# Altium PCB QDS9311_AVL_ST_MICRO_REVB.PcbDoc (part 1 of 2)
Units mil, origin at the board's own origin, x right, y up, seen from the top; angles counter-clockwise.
Board outline 2100 x 2774 mil, 6 copper layers (Top Layer, GND, INT1, PWR1, PWR2, Bottom Layer), stack 63.834 mil thick; 64 components, 29 nets, 286 pads, 246 vias.
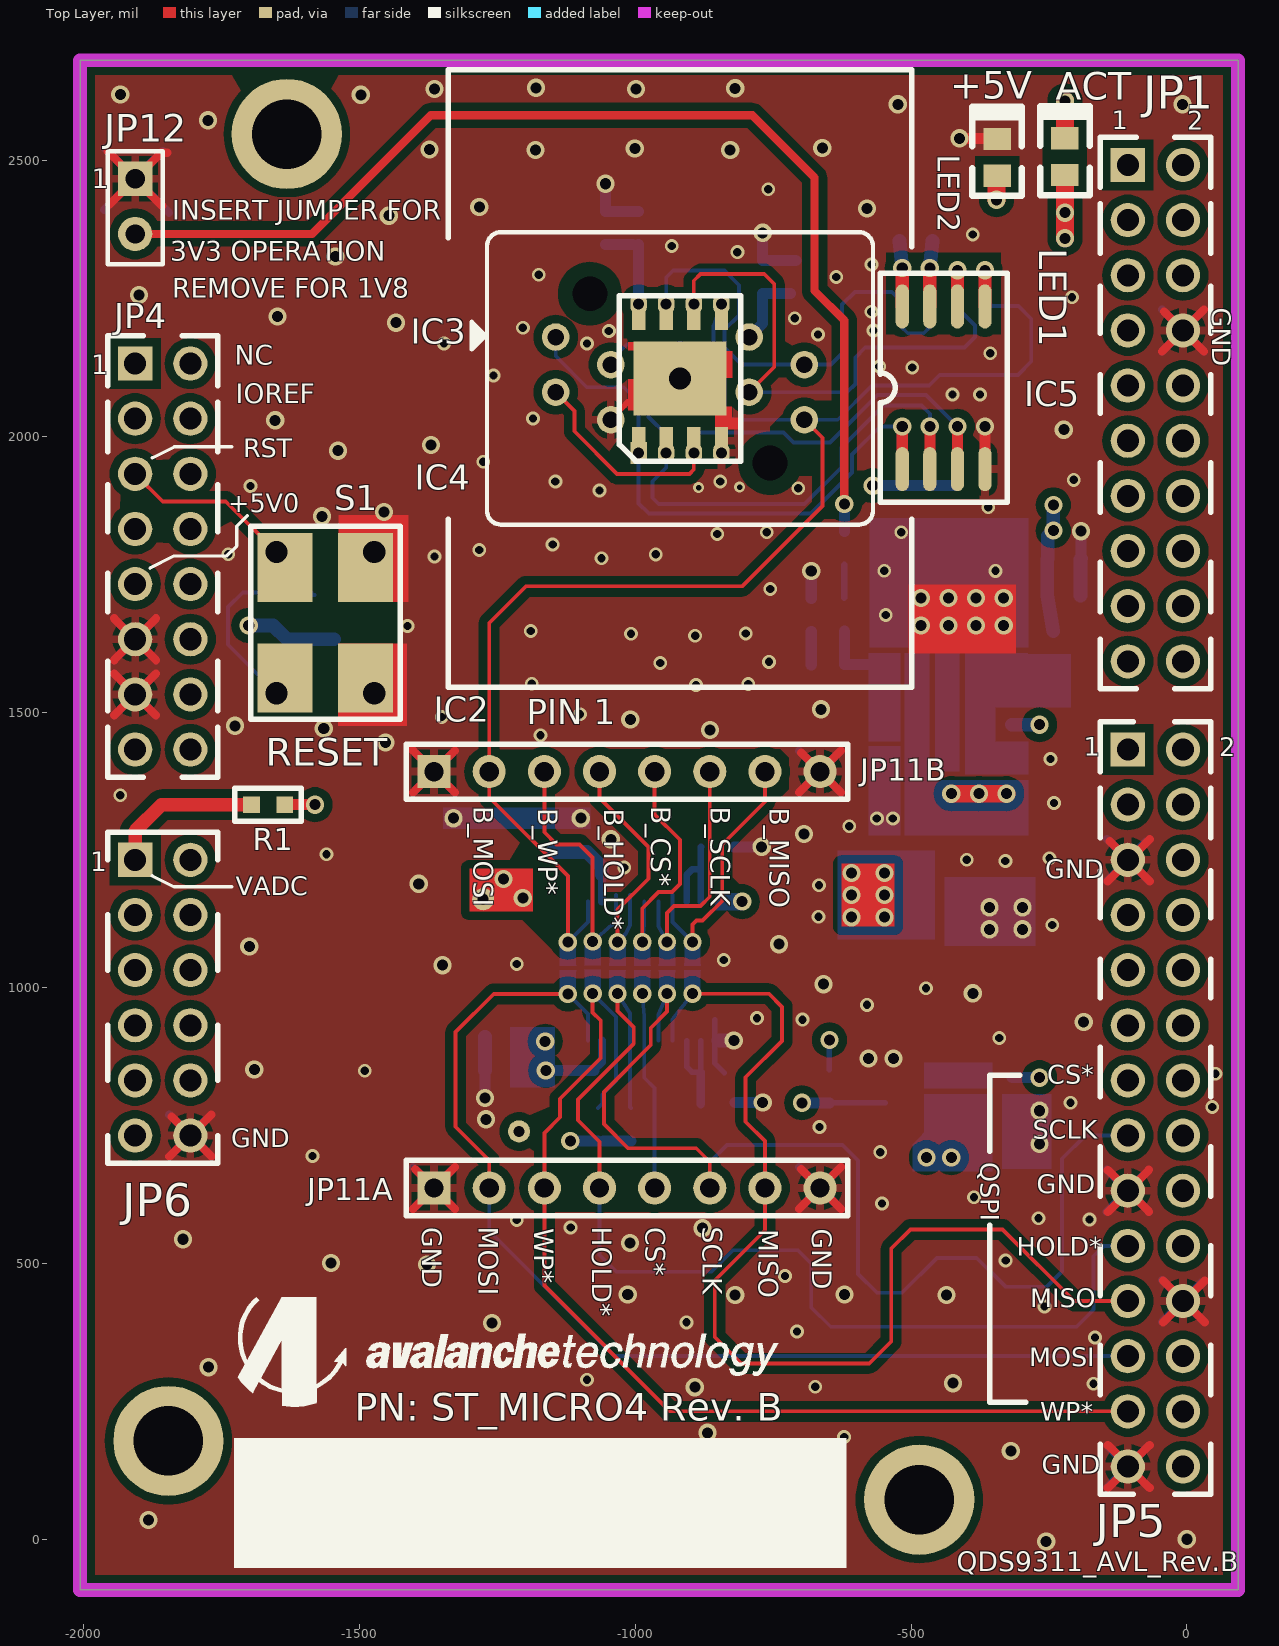
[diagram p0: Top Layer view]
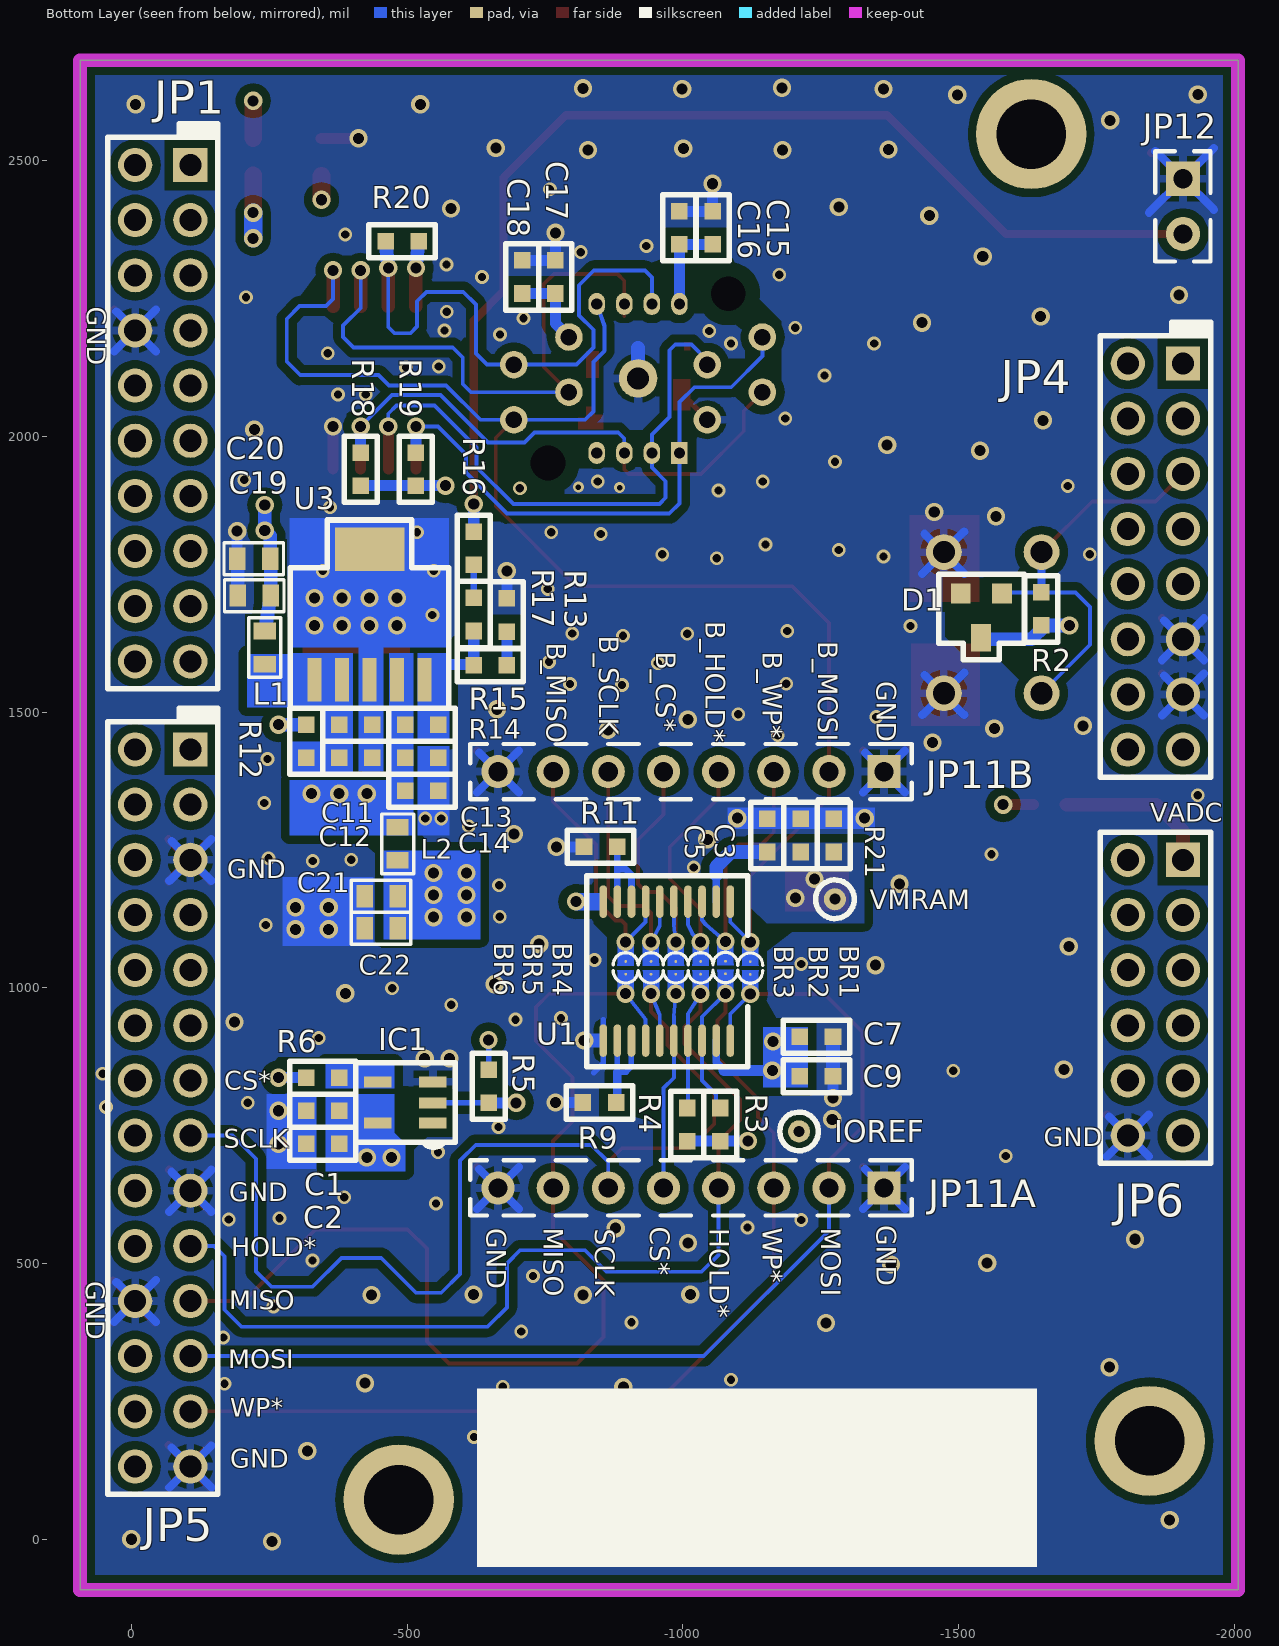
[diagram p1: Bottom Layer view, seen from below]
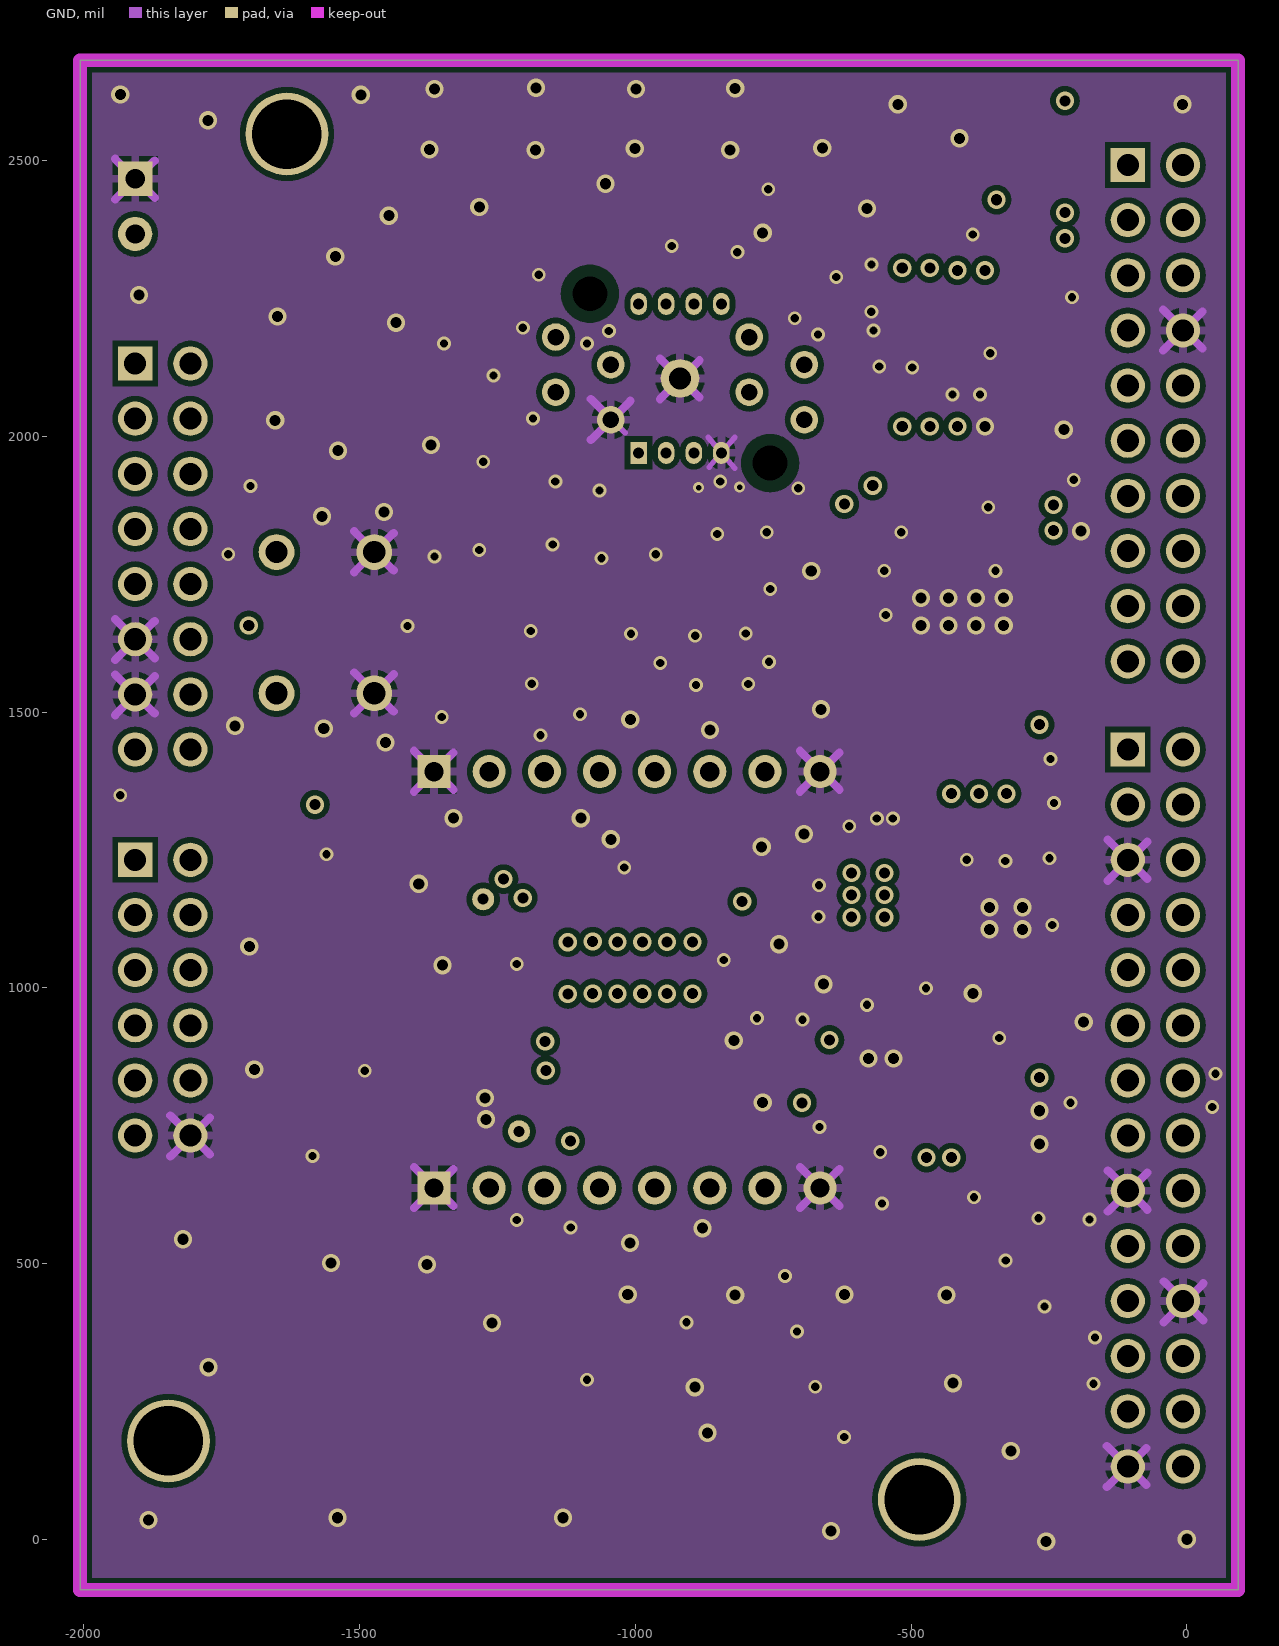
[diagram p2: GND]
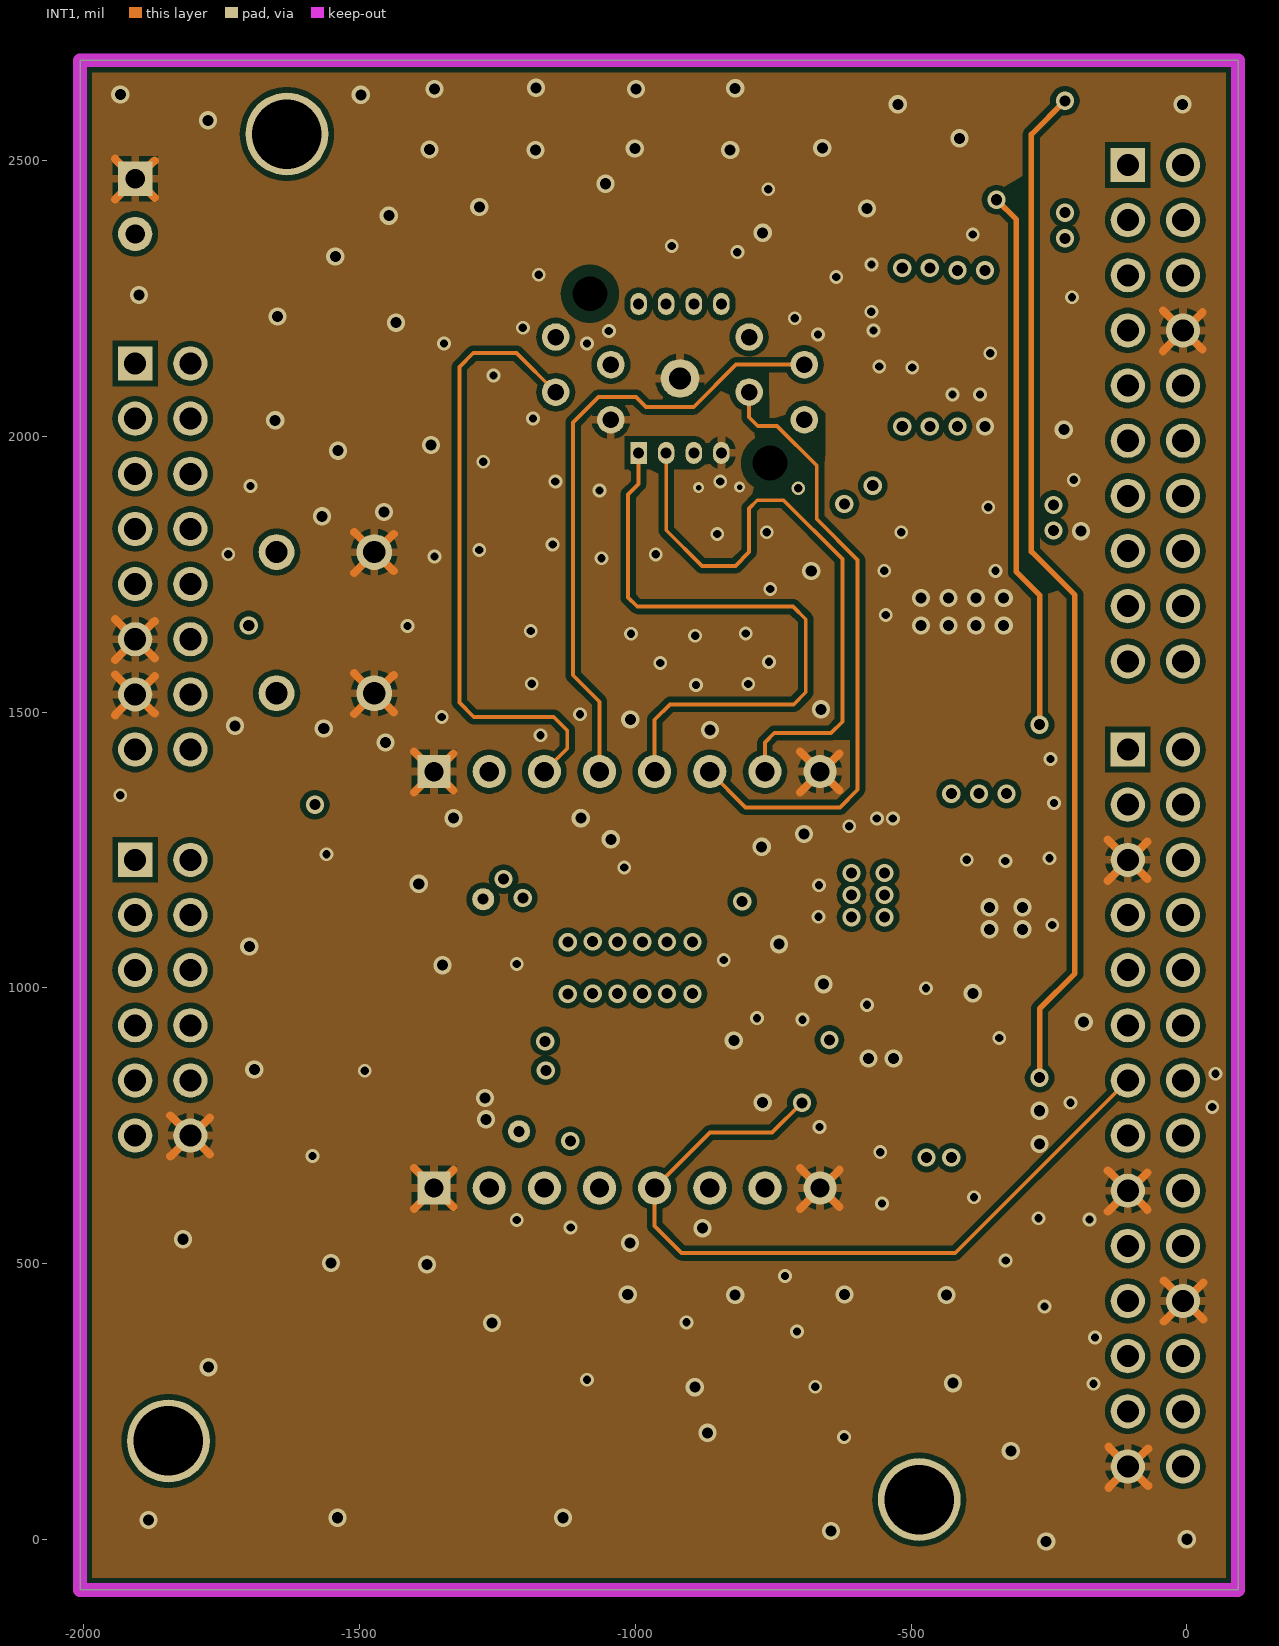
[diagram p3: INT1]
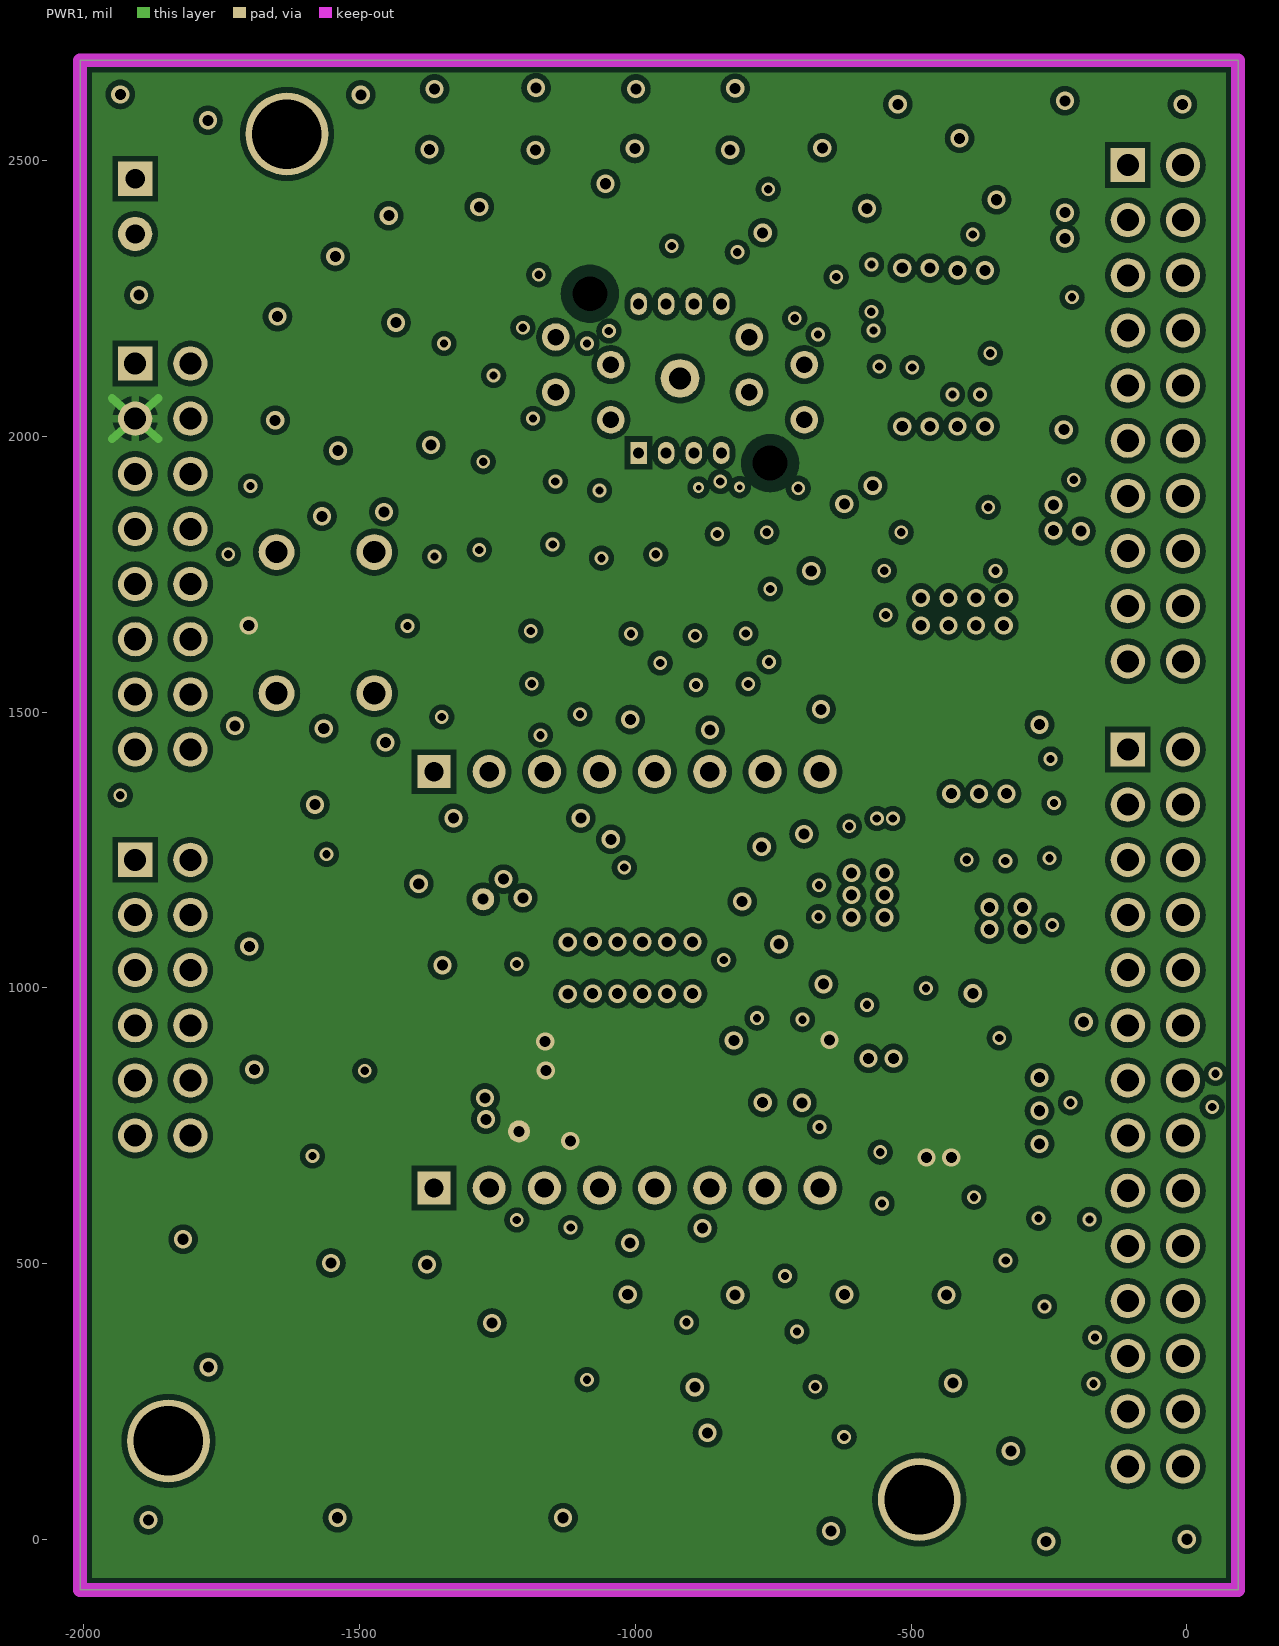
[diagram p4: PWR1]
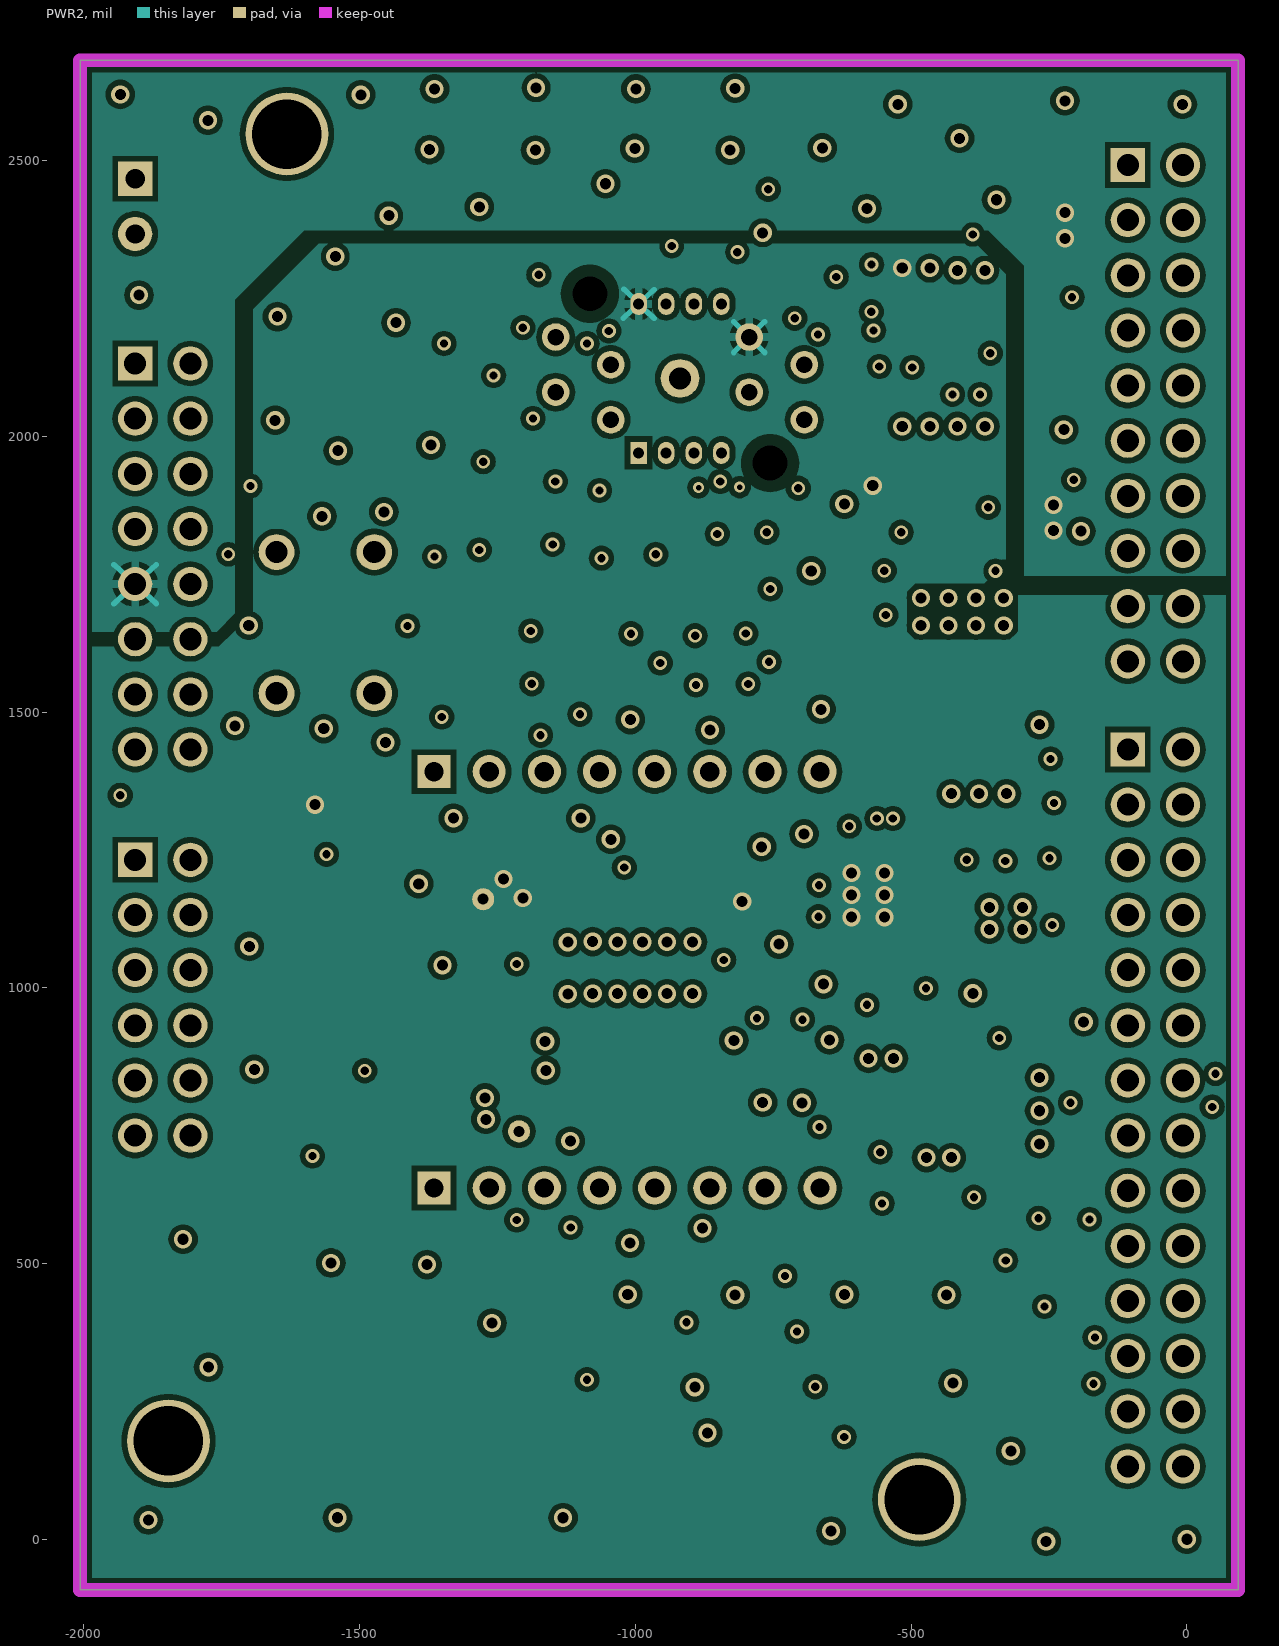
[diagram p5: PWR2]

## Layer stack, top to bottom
Top Solder: solder mask 1, Solder Resist, Dk 3.5
Top Layer: signal copper 6
Dielectric1: core 15, FR-4, Dk 4.2
GND: signal copper 2
Dielectric 8: prepreg 5, Dk 4.2
INT1: signal copper 1.417
Dielectric 10: core 10, Dk 4.2
PWR1: signal copper 2
Dielectric 11: prepreg 5, Dk 4.2
PWR2: signal copper 1.417
Dielectric 7: core 10, Dk 4.2
Bottom Layer: signal copper 6
Bottom Solder: solder mask 1, Solder Resist, Dk 3.5

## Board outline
-2007,-92 -2007,2682 93,2682 93,8 93,-92

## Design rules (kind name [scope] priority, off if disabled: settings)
Clearance Clearance_2 [OnLayer('Signal Layer 2')] p1 off: gap=10 ignorepadtopadclearanceinfootprint=FALSE except(0: Arc-Hole Track-Hole SMDPad-Hole THPad-Hole Via-Hole Fill-Hole Poly-Hole Region-Hole Text-Hole)
ComponentClearance [All] p1 off: gap=10 collisioncheckmode=3 verticalgap=10 showdistances=FALSE
FabricationTestPointUsage TestPointUsage [All] p1: valid=0 allowmultiple=FALSE
FabricationTestpoint Testpoint [(IsPad And (OnTopLayer Or OnBottomLayer))] p1: side=3 testpointundercomponent=TRUE minsize=40 maxsize=100 preferedsize=60 minholesize=0 maxholesize=40 preferedholesize=32 testpointgrid=1 allowsidetop=TRUE allowsidebottom=TRUE usegrid=TRUE gridtolerance=0.01
Height [All] p1 off: minheight=0 maxheight=1000 prefheight=500
HoleSize [All] p1 off: absolutevalues=TRUE maxlimit=100 minlimit=1 maxpercent=80.000 minpercent=20.000
PlaneConnect [All] p1: planeconnectstyle=Relief reliefexpansion=25 reliefentries=4 reliefconductorwidth=10 reliefairgap=12
PolygonConnect [All] p1: connectstyle=Direct reliefconductorwidth=10 reliefentries=4 polygonreliefangle="90 Angle" airgapwidth=10
RoutingVias [All] p1: holewidth=20 width=40 viastyle="Through Hole" minholewidth=20 minwidth=40 maxholewidth=20 maxwidth=40
ShortCircuit [InNet('NetA401_1') vs InNet('GND')] p1 off: allowed=FALSE
SolderMaskExpansion [All] p1: expansion=0 istentingtop=FALSE
Width Width_1 [All] p1: maxlimit=100 minlimit=6 preferedwidth=10 midlayer3_maxwidth=10 midlayer6_maxwidth=10 minimp=50.000000 maximp=50.000000 favimp=50.000000
23 further rules are at their usual default settings.

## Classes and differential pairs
net class GRP: C\S\ H\O\L\D\ MISO MOSI SCLK W\P\
net class B_GRP: B\_\C\S\ B\_\H\O\L\D\ B\_\W\P\ B_MISO B_MOSI B_SCLK
component class THERMAL: IC1 IC2 IC3 IC4 IC5 JP1 JP4 JP5 JP6 JP11A JP11B JP12 S1 U1 U3
component class PG0_ST_MICRO_4: BR1 BR2 BR3 BR4 BR5 BR6 C1 C2 C3 C5 C7 C9 D1 IC1 IOREF JP1 JP4 JP5 JP6 JP11A JP11B LED1 R1 R2 R3 R4 R5 R6 R9 R11 R21 S1 U1 VMRAM
component class PG1_ST_MICRO_4: C11 C12 C13 C14 C15 C16 C17 C18 C19 C20 C21 C22 IC2 IC3 IC4 IC5 JP12 L1 L2 LED2 R12 R13 R14 R15 R16 R17 R18 R19 R20 U3

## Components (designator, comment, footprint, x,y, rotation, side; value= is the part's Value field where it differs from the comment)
BR1 "NL" BR-603 -1122.39,1035.76 r90 bottom locked
BR2 "NL" BR-603 -1077.39,1036.76 r90 bottom locked
BR3 "NL" BR-603 -1032.37,1036.28 r90 bottom locked
BR4 "NL" BR-603 -987.39,1036.26 r90 bottom locked
BR5 "NL" BR-603 -942.42,1036.24 r90 bottom locked
BR6 "NL" BR-603 -896.42,1036.24 r90 bottom locked
C1 "10n" "0603 CAPACITOR_071713" -347,777 r0 bottom
C2 "1u" "0603 CAPACITOR_071713" -347,717 r0 bottom
C3 "10n" "0603 CAPACITOR_071713" -1213.55,1276.26 r90 bottom
C5 "1u" "0603 CAPACITOR_071713" -1153.55,1276.26 r90 bottom
C7 "10n" "0603 CAPACITOR_071713" -1242.39,911.26 r180 bottom
C9 "1u" "0603 CAPACITOR_071713" -1242.39,839.26 r180 bottom
C11 "10n" "0603 CAPACITOR_071713" -407,1477 r180 bottom
C12 "4.7u" "0603 CAPACITOR_071713" -407,1417 r180 bottom
C13 "10n" "0603 CAPACITOR_071713" -527,1417 r180 bottom
C14 "4.7u" "0603 CAPACITOR_071713" -527,1357 r180 bottom
C15 "1u" "0603 CAPACITOR_071713" -1054,2378 r90 bottom
C16 "10n" "0603 CAPACITOR_071713" -994,2378 r90 bottom
C17 "1u" "0603 CAPACITOR_071713" -769,2289 r90 bottom
C18 "10n" "0603 CAPACITOR_071713" -709,2289 r90 bottom
C19 "NL" 0603 -223,1711 r0 bottom
C20 "NL" 0603 -222,1778 r0 bottom
C21 "NL" 0603 -453,1166 r0 bottom
C22 "NL" 0603 -453,1108 r0 bottom
D1 "BAS40" SOT23_012105 -1541.5,1675 r0 bottom
IC1 "74LVC1G07DBVR" SOT25_030205 -497,792 r90 bottom
IC2 "AS2XXMA1G3A-WSON" "SOCKET WSON PLASTRONICS 08QN12T16050-M_020518" -919,2105 r90 top locked
IC3 "AS2XXMA1G3A-SOIC8" 652_SOP-1.27_8P -919,2105 r180 top locked
IC4 "AS2XXMA1G3A-WSON" "WSON8 6X5 MM WITH PAD_061714" -919,2105 r90 top locked
IC5 "AS2XXMA1G3A-SOIC8" "SO8 WIDE_071205" -441,2088 r0 top locked
IOREF "TP" "TEST POINT 40X20_010819" -1210.88,739.58 r270 bottom
JP1 "2X10_ML" 2X10-HEADER -57,2042 r270 top locked
JP4 "2X8_ML" 2X8-HEADER -1857,1782 r270 top locked
JP5 "2X14_ML" 2X14-HEADER -57,782 r270 top locked
JP6 "2X6_ML" "2X6 HEADER_082710" -1857,982 r270 top locked
JP11A "HEADER_8PIN" "1X8 HEADER ARDUINO STACKABLE_010719" -1015,637 r0 top locked
JP11B "HEADER_8PIN" "1X8 HEADER ARDUINO STACKABLE_010719" -1015,1392 r0 top locked
JP12 "3.3V ENABLE" "1X2 HEADER WITH SHUNT_051914" -1907,2467 r270 top
L1 "BLM18SG121TN1D" 0603 -242,1617 r270 bottom
L2 "BLM18SG121TN1D" 0603 -483,1261 r270 bottom
LED1 "GREEN" "LED 0805 GREEN_032906" -221,2507 r270 top locked
LED2 "RED" "LED 0805 GREEN_032906" -344,2506 r270 top
R1 "33" "0603 RESISTOR_071013" -1666,1332 r180 top
R2 "22K" "0603 RESISTOR_071013" -1650,1687 r270 bottom
R3 "22K" "0603 RESISTOR_071013" -1068,752 r270 bottom
R4 "22K" "0603 RESISTOR_071013" -1008,752 r270 bottom
R5 "22K" "0603 RESISTOR_071013" -648,821.5 r90 bottom
R6 "2K" "0603 RESISTOR_071013" -347,837 r0 bottom
R9 "100" "0603 RESISTOR_071013" -849,792 r180 bottom
R11 "100" "0603 RESISTOR_071013" -850.88,1255.58 r180 bottom
R12 "2K" "0603 RESISTOR_071013" -317,1447 r270 bottom
R13 "0" "0603 RESISTOR_071013" -681,1676 r90 bottom
R14 "105K, 1%" "0603 RESISTOR_071013" -527,1477 r0 bottom
R15 "30.9K, 1%" "0603 RESISTOR_071013" -651,1585 r0 bottom
R16 "0" "0603 RESISTOR_071013" -621,1797 r90 bottom
R17 "28.7K, 1%" "0603 RESISTOR_071013" -621,1677 r270 bottom
R18 "22K" "0603 RESISTOR_071013" -416,1940.5 r270 bottom
R19 "22K" "0603 RESISTOR_071013" -516,1940.5 r270 bottom
R20 "22K" "0603 RESISTOR_071013" -491,2354 r180 bottom
R21 "100K" "0603 RESISTOR_071013" -1273.55,1276.26 r270 bottom
S1 "SWRST" "SWITCH TE PB 1825910-6_112915" -1562,1662 r180 top locked
U1 "TXS0108E" TSSOP_20PIN -970.98,1030.26 r270 bottom locked
U3 "MCP1825T-ADJE/DC" "SOT223-6 REGULATOR_010419" -432,1677 r180 bottom
VMRAM "TP" "TEST POINT 40X20_010819" -1275.88,1160.58 r270 bottom

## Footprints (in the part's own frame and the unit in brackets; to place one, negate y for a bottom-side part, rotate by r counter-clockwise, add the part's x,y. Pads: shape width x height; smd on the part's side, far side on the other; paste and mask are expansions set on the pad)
"1X2 HEADER WITH SHUNT_051914" [mil] "TH"
  rect 62x62 hole 35: 1(0,0)
  round 62 hole 35: 2(100,0)
  silkscreen extent -50,-50 155,50
"1X8 HEADER ARDUINO STACKABLE_010719" [mil] "TH"
  rect 60x60 hole 35: 1(-350,0)
  round 60 hole 35: 2(-250,0) 3(-150,0) 4(-50,0) 5(50,0) 6(150,0) 7(250,0) 8(350,0)
  silkscreen extent -400,-50 400,50
"2X6 HEADER_082710" [mil] "TH"
  rect 62x62 hole 40: 1(-250,-50)
  round 62 hole 40: 2(-250,50) 3(-150,-50) 4(-150,50) 5(-50,-50) 6(-50,50) 7(50,-50) 8(50,50) 9(150,-50) 10(150,50) 11(250,-50) 12(250,50)
  silkscreen extent -300,-100 300,100
2X8-HEADER [mil] "TH"
  rect 62x62 hole 40: 1(-350,-50)
  round 62 hole 40: 2(-350,50) 3(-250,-50) 4(-250,50) 5(-150,-50) 6(-150,50) 7(-50,-50) 8(-50,50) 9(50,-50) 10(50,50) 11(150,-50) 12(150,50) 13(250,-50) 14(250,50) 15(350,-50) 16(350,50)
  silkscreen extent -400,-100 400,100
2X10-HEADER [mil] "TH"
  rect 62x62 hole 40: 1(-450,-50)
  round 62 hole 40: 2(-450,50) 3(-350,-50) 4(-350,50) 5(-250,-50) 6(-250,50) 7(-150,-50) 8(-150,50) 9(-50,-50) 10(-50,50) 11(50,-50) 12(50,50) 13(150,-50) 14(150,50) 15(250,-50) 16(250,50) 17(350,-50) 18(350,50) 19(450,-50) 20(450,50)
  silkscreen extent -500,-100 500,100
2X14-HEADER [mil] "TH"
  rect 62x62 hole 40: 1(-650,-50)
  round 62 hole 40: 2(-650,50) 3(-550,-50) 4(-550,50) 5(-450,-50) 6(-450,50) 7(-350,-50) 8(-350,50) 9(-250,-50) 10(-250,50) 11(-150,-50) 12(-150,50) 13(-50,-50) 14(-50,50) 15(50,-50) 16(50,50) 17(150,-50) 18(150,50) 19(250,-50) 20(250,50) 21(350,-50) 22(350,50) 23(450,-50) 24(450,50) 25(550,-50) 26(550,50) 27(650,-50) 28(650,50)
  silkscreen extent -700,-100 700,100
0603 [mil]
  rect 30x40 smd: 1(-30,0) 2(30,0)
  silkscreen extent -54,-29 54,29
"0603 CAPACITOR_071713" [mil] "SMT"
  rect 30x30 smd mask+2: 1(-30,0) 2(30,0)
  silkscreen extent -60,-30 60,30
"0603 RESISTOR_071013" [mil] "SM"
  rect 30x30 smd mask+2: 1(-30,0) 2(30,0)
  silkscreen extent -60,-30 60,30
652_SOP-1.27_8P [mil]
  round 50 hole 30: 1(225.39,-75) 2(125.39,-25) 3(225.39,25) 4(125.39,75) 5(-225.39,75) 6(-125.39,25) 7(-225.39,-25) 8(-125.39,-75)
  round 40 hole 63 unplated: HOLE1.6_NP(-163.39,153.54) HOLE1.6_NP(163.39,-153.54)
  round 40 on Mech2: HOLE1.6_NP(163.39,-153.54)
  round 50 on Mech2: ORIGIN(0,0)
  silkscreen extent -350,-265 378,265
BR-603 [mil] "BR-603"
  round 5 smd: 1(-11.5,0) 2(11.5,0)
  Top Layer region: 5.31,14.94 6.6,14.77 7.88,14.49 9.13,14.1 10.34,13.59 11.5,12.99 12.6,12.29 13.64,11.49 14.61,10.61 15.49,9.64 16.29,8.6 16.99,7.5 17.59,6.34 18.1,5.13 18.49,3.88 18.77,2.6 18.94,1.31 19,0 18.94,-1.31 18.77,-2.6 18.49,-3.88 18.1,-5.13 17.59,-6.34 16.99,-7.5 16.29,-8.6 15.49,-9.64 14.61,-10.61 13.64,-11.49 12.6,-12.29 11.5,-12.99 10.34,-13.59 9.13,-14.1 7.88,-14.49 6.6,-14.77 5.31,-14.94 4,-15 4,15
  Top Layer region: -4.04,-15 -5.35,-14.94 -6.64,-14.77 -7.92,-14.49 -9.17,-14.1 -10.38,-13.59 -11.54,-12.99 -12.64,-12.29 -13.68,-11.49 -14.65,-10.61 -15.53,-9.64 -16.33,-8.6 -17.03,-7.5 -17.63,-6.34 -18.14,-5.13 -18.53,-3.88 -18.81,-2.6 -18.98,-1.31 -19.04,0 -18.98,1.31 -18.81,2.6 -18.53,3.88 -18.14,5.13 -17.63,6.34 -17.03,7.5 -16.33,8.6 -15.53,9.64 -14.65,10.61 -13.68,11.49 -12.64,12.29 -11.54,12.99 -10.38,13.59 -9.17,14.1 -7.92,14.49 -6.64,14.77 -5.35,14.94 -4.04,15
  silkscreen extent -27,-23 27,23
"LED 0805 GREEN_032906" [mil] "SMT"
  rect 40x50 smd: A(33.46,0) C(-33.46,0)
  silkscreen extent -92,-45 70,45
"SO8 WIDE_071205" [mil] "SMT"
  oval 24x80 smd: 1(-75,-147.5) 2(-25,-147.5) 3(25,-147.5) 4(75,-147.5) 5(75,147.5) 6(25,147.5) 7(-25,147.5) 8(-75,147.5)
  silkscreen extent -115,-208 115,208, body extent -107,-160 107,159, height 69
"SOCKET WSON PLASTRONICS 08QN12T16050-M_020518" [mil] "TH"
  rect 40x30 hole 20: 1(-135,75)
  oval 40x30 hole 20: 2(-135,25) 3(-135,-25) 4_EP(-135,-75) 5(135,-75) 6(135,-25) 7(135,25) 8(135,75)
  round 70 hole 40 unplated: 9(0,0)
  silkscreen extent -560,-420 560,420, body extent -540,-400 540,400, height 570
SOT23_012105 [mil] "SMT"
  rect 36x36 smd: 1(-37.5,-40) 2(37.5,-40)
  rect 36x50 smd: 3(0.5,40)
  silkscreen extent -78,-75 78,80
SOT25_030205 [mil] "SMT"
  round 30 on Mech1 paste+0 mask+1.97: 1(-75,-65)
  rect 20x50 smd mask+1.97: 1(-37.5,-50) 2(-0.5,-50) 3(37.5,-50) 4(37.5,50) 5(-37.5,50)
  silkscreen extent -81,-90 72,90
"SOT223-6 REGULATOR_010419" [mm] "SMT"
  rect 0.65x2 smd mask+0.05: 1(-2.54,-3) 2(-1.27,-3) 3(0,-3) 4(1.27,-3) 5(2.54,-3)
  rect 3.2x2 smd: 3(0,3)
  silkscreen extent -3.65,-4.33 3.65,4.35
"SWITCH TE PB 1825910-6_112915" [mil] "TH"
  round 65 hole 40: 1(88.58,127.95) 2(88.58,-127.95) 3(-88.58,127.95) 4(-88.58,-127.95)
  rect 30x60 on Mech2: ""(-75,110) ""(-75,-110) ""(75,110) ""(75,-110)
  rect 100x125 smd mask-1000: ""(-73,100) ""(-73,-100) ""(73,100) ""(73,-100)
  rect 50x70 on Mech2 mask-1000: ""(-50,75) ""(-50,-75) ""(50,75) ""(50,-75)
  round 60 on Mech2: ""(0,0)
  silkscreen extent -136,-175 136,175
"TEST POINT 40X20_010819" [mil] "TH"
  round 40 hole 20: 1(0,0)
  silkscreen extent -35,-35 35,35
TSSOP_20PIN [mm] "SM FP"
  oval 1.5x0.35 smd mask+0.038: 1(-3.2,2.925) 2(-3.2,2.275) 3(-3.2,1.625) 4(-3.2,0.975) 5(-3.2,0.325) 6(-3.2,-0.325) 7(-3.2,-0.975) 8(-3.2,-1.625) 9(-3.2,-2.275) 10(-3.2,-2.925) 11(3.2,-2.925) 12(3.2,-2.275) 13(3.2,-1.625) 14(3.2,-0.975) 15(3.2,-0.325) 16(3.2,0.325) 17(3.2,0.975) 18(3.2,1.625) 19(3.2,2.275) 20(3.2,2.925)
  silkscreen extent -4.4,-3.68 4.4,3.73
"WSON8 6X5 MM WITH PAD_061714" [mil] "SMT"
  rect 50x24 smd mask+2: 1(-113.11,75) 2(-113.11,25) 3(-113.11,-25) 4_EP(-113.11,-75) 5(113.11,-75) 6(113.11,-25) 7(113.11,25) 8(113.11,75)
  rect 133.86x169.29 smd paste-95 mask+0: 9(0,0)
  silkscreen extent -150,-110 150,110, body extent -117,-98 119,98, height 30

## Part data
BR1 BR2 BR3 BR4 BR5 BR6: library part R-US_R0805, "<B>RESISTOR</B>, American symbol"
C1 C2 C3 C5 C7 C9 C11 C12 C13 C14 C15 C16 C17 C18: library part C-USC0603, "<B>CAPACITOR</B>, American symbol"
C19 C20 C21 C22: library part C-USC0805, "<B>CAPACITOR</B>, American symbol"
D1: "<b>Silicon Schottky Diodes</b><p> / General-purpose diode for high-speed switching"
IC2 IC4: "AVALANCHE TECHNOLOGY SPI SPnvSRAM - WSON 8 PACKAGE"
IC3 IC5: "AVALANCHE TECHNOLOGY SPI SPnvSRAM - SOIC8 PACKAGE"
IOREF VMRAM: library part "TEST POINT 1"
JP12: library part PINHD-1X2, "<b>PIN HEADER</b>"
L1 L2: library part FB
LED1 LED2: library part LEDCHIP-LED0805, "<b>LED</b><p> / <u>OSRAM</u>:<br> /  / - <u>CHIPLED</u><br> / LG R971, LG N971, LY N971, LG Q971, LY Q971, LO R971, LY R971 / LH N974, LH R974<br> / LS Q976, LO Q976, LY Q976<br> / LO Q996<br> /  / - <u>Hyper CHIPLED</u><br> / LW Q18S<br> / LB Q993, LB Q99A, LB R99A<br> /  / - <u>SideLED</u><br> / LS A670, LO A670, LY A670, LG A670, LP A670<br> / LB A673, LV A673, LT A673, LW A673<br> / LH A674<br> / LY A675<br> / LS A676, LA A676, LO A676, LY A676, LW A676<br> / LS A679, LY A679, LG A679<br> /  / -  <u>Hyper Micro SIDELED®</u><br> / LS Y876, LA Y876, LO Y876, LY Y876<br> / LT Y87S<br> /  / - <u>SmartLED</u><br> / LW L88C, LW L88S<br> / LB L89C, LB L89S, LG L890<br> / LS L89K, LO L89K, LY L89K<br> / LS L896, LA L896, LO L896, LY L896<br> /  / - <u>TOPLED</u><br> / LS T670, LO T670, LY T670, LG T670, LP T670<br> / LSG T670, LSP T670, LSY T670, LOP T670, LYG T670<br> / LG T671, LOG T671, LSG T671<br> / LB T673, LV T673, LT T673, LW T673<br> / LH T674<br> / LS T676, LA T676, LO T676, LY T676, LB T676, LH T676, LSB T676, LW T676<br> / LB T67C, LV T67C, LT T67C, LS T67K, LO T67K, LY T67K, LW E67C<br> / LS E67B, LA E67B, LO E67B, LY E67B, LB E67C, LV E67C, LT E67C<br> / LW T67C<br> / LS T679, LY T679, LG T679<br> / LS T770, LO T770, LY T770, LG T770, LP T770<br> / LB T773, LV T773, LT T773, LW T773<br> / LH T774<br> / LS E675, LA E675, LY E675, LS T675<br> / LS T776, LA T776, LO T776, LY T776, LB T776<br> / LHGB T686<br> / LT T68C, LB T68C<br> /  / - <u>Hyper Mini TOPLED®</u><br> / LB M676<br> /  / - <u>Mini TOPLED Santana®</u><br> / LG M470<br> / LS M47K, LO M47K, LY M47K / <p> / Source: http://www.osram.convergy.de<p> /  / <u>LUXEON:</u><br> / - <u>LUMILED®</u><br> / LXK2-PW12-R00, LXK2-PW12-S00, LXK2-PW14-U00, LXK2-PW14-V00<br> / LXK2-PM12-R00, LXK2-PM12-S00, LXK2-PM14-U00<br> / LXK2-PE12-Q00, LXK2-PE12-R00, LXK2-PE12-S00, LXK2-PE14-T00, LXK2-PE14-U00<br> / LXK2-PB12-K00, LXK2-PB12-L00, LXK2-PB12-M00, LXK2-PB14-N00, LXK2-PB14-P00, LXK2-PB14-Q00<br> / LXK2-PR12-L00, LXK2-PR12-M00, LXK2-PR14-Q00, LXK2-PR14-R00<br> / LXK2-PD12-Q00, LXK2-PD12-R00, LXK2-PD12-S00<br> / LXK2-PH12-R00, LXK2-PH12-S00<br> / LXK2-PL12-P00, LXK2-PL12-Q00, LXK2-PL12-R00 / <p> / Source: www.luxeon.com<p> /  / <u>KINGBRIGHT:</U><p> / KA-3528ASYC<br> / Source: www.kingbright.com"
R1 R2 R3 R4 R5 R6 R9 R11 R12 R13 R14 R15 R16 R17 R18 R19 R20 R21: library part R-US_R0603, "<B>RESISTOR</B>, American symbol"
S1: library part MOMENTARY-SWITCH-SPST-2-SMD-5.2MM, "<h3>Momentary Switch (Pushbutton) - SPST - Two Circuits</h3> / <p>Normally-open (NO) SPST momentary switches (buttons, pushbuttons). Schematic symbol includes two switch circuits.</p> / <h4>Variants</h4> / <ul> / <li><b>SMD-4.6MMX2.8MM</b> -  4.60mm x 2.80mm Tactile Momentary Button Switch  - Used on <a href=\"https://www.sparkfun.com/products/13664\">SparkFun SAMD21 Mini Breakout</a></li> / <li><b>SMD-5.2MM</b> - <a href=\"https://www.sparkfun.com/products/8720\">Mini Pushbutton Switch - SMD</a> - Used on <a href=\"https://www.sparkfun.com/products/11114\">Arduino Pro Mini</a></li> / </ul>"

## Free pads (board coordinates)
  round 45 on Bottom Overlay: 2(-585,681) ""(-1152.39,1152.26)
  round 60 on Mech9: ""(-1907,1232) ""(-1907,2132)
  round 200 / inner round 150 / far side round 200 hole 126 mask+0: ""(-1846.64,178.28) ""(-1631.86,2548.18) ""(-485.17,71.9)
  round 45 on Top Overlay: ""(-1706,1444)

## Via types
v1: diameter 33, hole 20, Top Layer to Bottom Layer, tented both sides, 143 vias
v2: diameter 25, hole 15, Top Layer to Bottom Layer, tented both sides, 101 vias
v3: diameter 20, hole 10, Top Layer to Bottom Layer, tented both sides, 2 vias

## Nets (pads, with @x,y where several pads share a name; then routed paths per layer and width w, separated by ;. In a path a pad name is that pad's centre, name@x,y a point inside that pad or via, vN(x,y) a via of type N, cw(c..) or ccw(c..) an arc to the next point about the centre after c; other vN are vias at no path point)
+5V0: C19.1 C20.1 JP4.9 L1.1 LED1.A | length 604.7
  Top Layer w32: v1(-221,2359) v1(-221,2405.54) LED1.A@-221,2473.54
  PWR2 w10: -1945.5,1696.46 JP4.9@-1907,1732 ; -1945.5,1767.54 JP4.9@-1907,1732 ; -1868.5,1696.46 JP4.9@-1907,1732 ; -1868.5,1767.54 JP4.9@-1907,1732
  Bottom Layer w25: L1.1@-242,1647 C19.1@-253,1711 -253,1777 C20.1@-252,1778 -252,1819 v1(-242,1829) v1(-242,1875.54)
  Bottom Layer w33: v1(-221,2359) v1(-221,2405.54)
B\_\C\S\: BR4.2 IC2.1 IC3.1 IC4.1 IC5.1 JP11B.5 R19.1 U1.5 | length 2728.9
  Top Layer w7: IC2.1@-994,1970 IC4.1@-994,1991.89 ; v1(-987.39,1083.21) -987.39,1144.02 -957.79,1173.62 -933.75,1173.62 -919,1188.37 -919,1268.42 -965,1314.42 JP11B.5@-965,1392
  Top Layer w20: IC5.1@-516,1940.5 v1(-516,2018)
  INT1 w7: IC2.1@-994,1970 -994,1913.22 -1013,1894.22 -1013,1707.76 -996.51,1691.26 -713.99,1691.26 -691,1668.28 -691,1535.8 -712.8,1514 -937.12,1514 -965,1486.12 JP11B.5@-965,1392
  Bottom Layer w7: IC3.1@-1144.39,2180 -1144.39,2145.39 -1088,2089 -1021,2089 -994,2062 IC2.1@-994,1970 -994,1878.49 -975.51,1860 -681.21,1860 -607,1934.21 -607,1967 -556,2018 v1(-516,2018) ; BR4.2@-987.39,1047.76 v1(-987.39,1083.21) -983.78,1114.49 U1.5@-983.78,1156.24
  Bottom Layer w20: R19.1@-516,1970.5 v1(-516,2018)
B\_\H\O\L\D\: BR3.2 IC2.7 IC3.7 IC4.7 IC5.7 JP11B.4 R20.1 U1.4 | length 2727.7
  Top Layer w7: JP11B.4@-1065,1392 -1065,1344 -976.34,1255.34 -976.34,1197.66 -1032.37,1141.63 v1(-1032.37,1083.24)
  Top Layer w24: IC5.7@-466,2235.5 v1(-466,2305)
  INT1 w7: JP11B.4@-1065,1392 -1065,1518.73 -1113,1566.73 -1113,2024.92 -1066.75,2071.17 -998.67,2071.17 -980.5,2053 -894.14,2053 -817.14,2130 IC3.7@-693.61,2130
  Bottom Layer w7: BR3.2@-1032.37,1047.78 -1032.37,1083.14 v1(-1032.37,1083.24) -1017.75,1097.75 -1009.37,1114.69 U1.4@-1009.37,1156.24 U1.4@-1009.37,1168.2 ; IC2.7@-944,2240 -944,2287.73 -931.23,2300.5 -838.64,2300.5 -812,2273.86 -812,2219.17 -838,2193.17 -838,2160.72 -807.28,2130 IC3.7@-693.61,2130 -645,2130 -625,2150 -625,2239 -602,2262 -535,2262 -518,2245 -518,2199 -506,2187 -477,2187 -466,2198 v1(-466,2305)
  Bottom Layer w25: v1(-466,2305) R20.1@-461,2354
B\_\W\P\: BR2.2 IC2.3 IC3.3 IC4.3 IC5.3 JP11B.3 R18.1 U1.3 | length 2729.3
  Top Layer w7: JP11B.3@-1165,1392 -1165,1282 -1143,1260 -1101.31,1260 -1077.39,1236.09 v1(-1077.39,1083.71) ; IC3.3@-1144.39,2080 -1110.5,2046.11 -1110.5,2009.12 -1033.07,1931.69 -901.86,1931.69 -894,1939.55 IC2.3@-894,1970 IC4.3@-894,1991.89 ; v1@-1077.92,1083.19 v1@-1077.39,1082.66
  Top Layer w20: IC5.3@-416,1940.5 v1(-416,2018)
  INT1 w7: JP11B.3@-1165,1392 -1123.39,1433.61 -1123.39,1466.39 -1148,1491 -1293,1491 -1319,1517 -1319,2126 -1294,2151 -1215.39,2151 IC3.3@-1144.39,2080
  Bottom Layer w7: BR2.2@-1077.39,1048.26 v1(-1077.39,1083.71) -1041.62,1114.69 -1034.96,1122.97 U1.3@-1034.96,1156.24 U1.3@-1034.96,1168.2 ; IC2.3@-894,1970 -894,1996 -883,2007 -731,2007 -713,1989 -647,1989 -561,2075 -473,2075 v1(-416,2018)
  Bottom Layer w20: R18.1@-416,1970.5 v1(-416,2018)
B_MISO: BR6.2 IC2.2 IC3.2 IC4.2 IC5.2 JP11B.7 U1.7 | length 2729
  Top Layer w7: v1(-896.42,1083.19) -896.42,1114.58 -889,1122 -878,1122 -842.43,1157.57 -842.43,1259.88 -765,1337.31 JP11B.7@-765,1392
  Top Layer w20: IC5.2@-466,1940.5 v1(-466,2018)
  INT1 w7: IC2.2@-944,1970 -944,1829.68 -879.32,1765 -818.59,1765 -793.61,1789.99 -793.61,1869.39 -779,1884 -731,1884 -624.67,1777.67 -624.67,1482.33 -645,1462 -748,1462 -765,1445 JP11B.7@-765,1392
  Bottom Layer w7: IC3.2@-1044.39,2130 -1044.39,2137.83 -1015.67,2166.56 -986.39,2166.56 -976,2156.16 -976,2035 -944,2003 IC2.2@-944,1970 -944,1943.5 -969,1918.5 -969,1888.5 -957.5,1877 -693,1877 -626,1944 -626,1980 -550,2056 -481,2056 -466,2041 v1(-466,2018) ; U1.7@-932.6,1168.2 U1.7@-932.6,1156.24 -932.6,1119.37 v1(-896.42,1083.19) BR6.2@-896.42,1047.74
B_MOSI: BR1.2 IC2.5 IC3.5 IC4.5 IC5.5 JP11B.2 U1.1 | length 2729.6
  Top Layer w7: v1(-1122.39,1082.71) -1122.39,1202.39 -1265,1345 JP11B.2@-1265,1392 -1265,1661.8 -1198.8,1728 -806.26,1728 -660.94,1873.32 -660.94,1997.33 IC3.5@-693.61,2030
  Top Layer w24: IC5.5@-366,2235.5 v1(-366,2301)
  Bottom Layer w7: BR1.2@-1122.39,1047.26 v1(-1122.39,1082.71) -1086.14,1118.96 U1.1@-1086.14,1156.24 ; IC2.5@-844,2240 -858,2200 -858,2155.04 -838,2135.04 -838,2045 -823,2030 IC3.5@-693.61,2030 -633,2030 -571,2092 -467,2092 -448,2111 -306.37,2111 -282,2135.37 -282,2213 -305.2,2236.2 -353.2,2236.2 -366,2249 v1(-366,2301)
B_SCLK: BR5.2 IC2.6 IC3.6 IC4.6 IC5.6 JP11B.6 U1.6 | length 2728.9
  Top Layer w7: v1(-942.42,1083.19) -942.42,1135.49 -929.91,1148 -882,1148 -865,1165 JP11B.6@-865,1392 ; IC4.6@-894,2218.11 IC2.6@-894,2240 -894,2282 -881.76,2294.24 -766.24,2294.24 -748,2276 -748,2125.61 IC3.6@-793.61,2080
  Top Layer w24: IC5.6@-416,2235.5 v1(-416,2301)
  INT1 w7: JP11B.6@-865,1392 -800,1327 -629,1327 -597,1359 -597,1776.01 -671,1850.01 -671,1947 -743,2019 -778,2019 -793.61,2034.61 IC3.6@-793.61,2080
  Bottom Layer w7: U1.6@-958.19,1156.24 -958.19,1112.26 v1(-942.42,1083.19) BR5.2@-942.42,1047.74 ; IC3.6@-793.61,2080 -616,2080 -601,2095 -601,2143 -583,2161 -403,2161 -384,2180 -384,2200.96 -416,2232.96 v1(-416,2301)
C\S\: BR4.1 IC1.2 JP5.13 JP11A.5 R5.1 U1.16 | length 1954.6
  INT1 w7: v1(-698,791.5) -751.88,737.62 -864.38,737.62 JP11A.5@-965,637 -965,568 -916,519 -420,519 JP5.13@-107,832
  Bottom Layer w7: BR4.1@-987.39,1024.76 v1(-987.39,989.31) -983.78,948.26 U1.16@-983.78,904.27 -983.78,836.78 -965,818 JP11A.5@-965,637
  Bottom Layer w10: R5.1@-648,791.5 IC1.2@-547,791.5
  Bottom Layer w20: v1(-698,791.5) R5.1@-648,791.5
